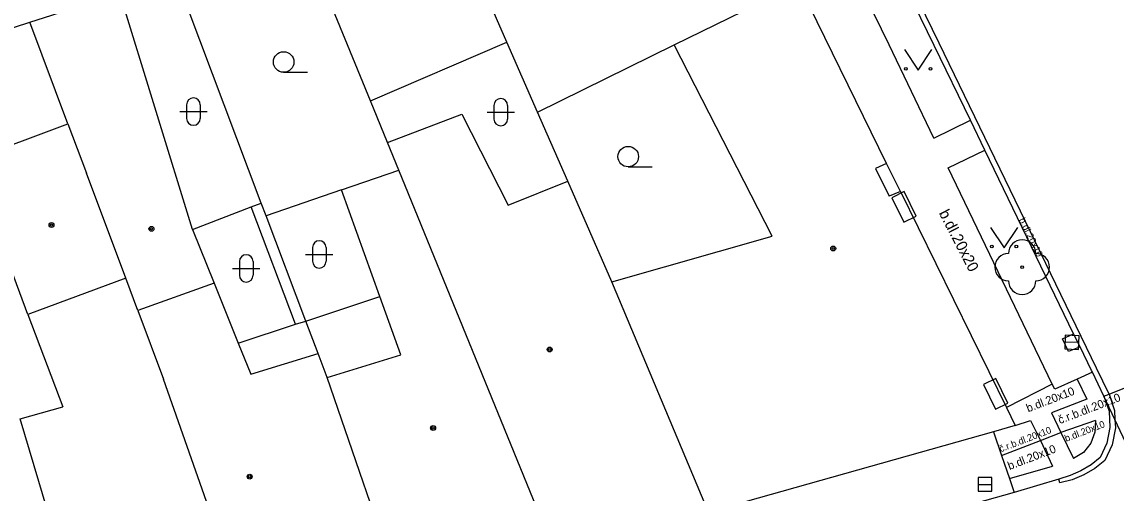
# Model space of a CAD drawing. Extents: x -595546 to -593986, y -1160845 to -1159202.
# Drawn here: x -595474.42 to -595434.45, y -1160188.2 to -1160170.97 of the extents above; entities that cross this region are included whole.
import ezdxf

# ---------------------------------------------------------------- set-up
doc = ezdxf.new("R2010")
doc.units = 0
for name, color, linetype in [('DOP - kresba z DSPS bez souradnic', 7, 'Continuous'), ('DOP - rozhrani ploch obecne', 7, 'Continuous'), ('Level 22', 7, 'Continuous'), ('Level 24', 7, 'Continuous'), ('Level 27', 7, 'Continuous'), ('Level 36', 7, 'Continuous'), ('Level 39', 7, 'Continuous'), ('Specificka linie pasportu komunikaci', 7, 'Continuous'), ('TM - budovy zdene_ betonove - NP', 7, 'Continuous'), ('TM - budovy zdene_ betonove - VP', 7, 'Continuous'), ('TM - chodniky - VP', 7, 'Continuous'), ('TM - komunikace - VP', 7, 'Continuous'), ('TM - letecke snimky - pomocna linie', 7, 'Continuous'), ('TM - pomocna konstrukcni linie', 7, 'Continuous'), ('TM - popis povrchu', 7, 'Continuous'), ('TM - rozhrani mezi zpev. plochami mezi sebou - VP', 7, 'Continuous'), ('TM - vstup do budovy - zdene_ betonove', 7, 'Continuous')]:
    doc.layers.add(name, color=color, linetype=linetype)

msp = doc.modelspace()

# ---------------------------------------------------------------- linework, layer by layer
at = {"layer": 'DOP - kresba z DSPS bez souradnic'}
for points in [[(-595461.69, -1160173.86), (-595456.7, -1160171.72)], [(-595462.75, -1160177.11), (-595465.5, -1160178.06)], [(-595466.04, -1160177.74), (-595465.68, -1160177.6)], [(-595468.19, -1160178.57), (-595466.04, -1160177.74)], [(-595464.43, -1160182.02), (-595466.04, -1160177.74)], [(-595464.05, -1160181.91), (-595461.34, -1160181.01)], [(-595466.52, -1160182.72), (-595464.43, -1160182.02)], [(-595464.43, -1160182.02), (-595464.05, -1160181.91)]]:
    msp.add_lwpolyline(points, dxfattribs=at)
at = {"layer": 'DOP - rozhrani ploch obecne'}
for points in [[(-595456.7, -1160171.72), (-595459.14, -1160166.13)], [(-595461.69, -1160173.86), (-595464.18, -1160167.77)], [(-595465.68, -1160177.6), (-595468.81, -1160169.27)], [(-595474.13, -1160170.99), (-595470.84, -1160169.92)], [(-595478.73, -1160172.48), (-595474.13, -1160170.99)], [(-595472.74, -1160174.7), (-595474.13, -1160170.99)], [(-595455.59, -1160174.27), (-595456.7, -1160171.72)], [(-595455.59, -1160174.27), (-595450.59, -1160171.81)], [(-595461.06, -1160175.39), (-595461.69, -1160173.86)], [(-595454.48, -1160176.8), (-595455.59, -1160174.27)], [(-595465.5, -1160178.06), (-595465.68, -1160177.6)], [(-595464.05, -1160181.91), (-595465.5, -1160178.06)], [(-595463.6, -1160183.1), (-595464.05, -1160181.91)]]:
    msp.add_lwpolyline(points, dxfattribs=at)
at = {"layer": 'Level 22'}
msp.add_circle((-595437.88, -1160179.94), 0.05, dxfattribs=at)
for centre, start, end in [((-595437.88, -1160179.44), 0, 180), ((-595438.38, -1160179.94), 90, 270), ((-595437.38, -1160179.94), 270, 90), ((-595437.88, -1160180.44), 180, 0)]:
    msp.add_arc(centre, 0.5, start, end, dxfattribs=at)
at = {"layer": 'Level 24'}
for points in [[(-595441.751, -1160178.079), (-595442.191, -1160177.181), (-595442.64, -1160177.401), (-595442.2, -1160178.299)], [(-595438.403, -1160184.908), (-595438.843, -1160184.01), (-595439.292, -1160184.23), (-595438.852, -1160185.128)]]:
    msp.add_lwpolyline(points, close=True, dxfattribs=at)
at = {"layer": 'Level 27'}
for p, q in [((-595435.81, -1160182.699), (-595436.31, -1160182.681)), ((-595439.48, -1160187.88), (-595438.98, -1160187.88))]:
    msp.add_line(p, q, dxfattribs=at)
for points in [[(-595435.801, -1160182.449), (-595436.301, -1160182.431), (-595436.319, -1160182.931), (-595435.819, -1160182.949)], [(-595439.48, -1160188.13), (-595438.98, -1160188.13), (-595438.98, -1160187.63), (-595439.48, -1160187.63)]]:
    msp.add_lwpolyline(points, close=True, dxfattribs=at)
at = {"layer": 'Level 36'}
for p, q in [((-595464.86, -1160172.815), (-595463.985, -1160172.815)), ((-595468.406, -1160174.006), (-595468.406, -1160174.506)), ((-595467.906, -1160174.006), (-595467.906, -1160174.506)), ((-595457.176, -1160174.026), (-595457.176, -1160174.526)), ((-595456.676, -1160174.026), (-595456.676, -1160174.526)), ((-595468.656, -1160174.256), (-595467.656, -1160174.256)), ((-595457.426, -1160174.276), (-595456.426, -1160174.276)), ((-595452.27, -1160176.275), (-595451.395, -1160176.275)), ((-595463.806, -1160179.226), (-595463.806, -1160179.726)), ((-595463.306, -1160179.226), (-595463.306, -1160179.726)), ((-595464.056, -1160179.476), (-595463.056, -1160179.476)), ((-595466.726, -1160179.986), (-595465.726, -1160179.986)), ((-595466.476, -1160179.736), (-595466.476, -1160180.236)), ((-595465.976, -1160179.736), (-595465.976, -1160180.236))]:
    msp.add_line(p, q, dxfattribs=at)
for points in [[(-595442.18, -1160171.99), (-595441.68, -1160172.74), (-595441.18, -1160171.99)], [(-595439.04, -1160178.49), (-595438.54, -1160179.24), (-595438.04, -1160178.49)]]:
    msp.add_lwpolyline(points, dxfattribs=at)
for centre, radius in [((-595464.86, -1160172.44), 0.375), ((-595442.13, -1160172.69), 0.05), ((-595441.231, -1160172.69), 0.05), ((-595452.27, -1160175.9), 0.375), ((-595438.99, -1160179.19), 0.05), ((-595438.091, -1160179.19), 0.05)]:
    msp.add_circle(centre, radius, dxfattribs=at)
for centre, start, end in [((-595468.156, -1160174.006), 0, 180), ((-595456.926, -1160174.026), 0, 180), ((-595468.156, -1160174.506), 180, 0), ((-595456.926, -1160174.526), 180, 0), ((-595463.556, -1160179.226), 0, 180), ((-595466.226, -1160179.736), 0, 180), ((-595463.556, -1160179.726), 180, 0), ((-595466.226, -1160180.236), 180, 0)]:
    msp.add_arc(centre, 0.25, start, end, dxfattribs=at)
at = {"layer": 'Level 39'}
for centre, radius in [((-595473.34, -1160178.4), 0.09), ((-595473.34, -1160178.4), 0.0398), ((-595469.69, -1160178.54), 0.09), ((-595469.69, -1160178.54), 0.0398), ((-595444.78, -1160179.26), 0.09), ((-595444.78, -1160179.26), 0.0398), ((-595455.14, -1160182.95), 0.09), ((-595455.14, -1160182.95), 0.0398), ((-595459.4, -1160185.82), 0.09), ((-595459.4, -1160185.82), 0.0398), ((-595466.1, -1160187.6), 0.09), ((-595466.1, -1160187.6), 0.0398)]:
    msp.add_circle(centre, radius, dxfattribs=at)
at = {"layer": 'Specificka linie pasportu komunikaci'}
for points in [[(-595434.7, -1160184.58), (-595428.76, -1160182.2)], [(-595434.89, -1160184.66), (-595434.7, -1160184.58)], [(-595434.49, -1160185.51), (-595434.89, -1160184.66)], [(-595430.18, -1160194.66), (-595434.49, -1160185.51)]]:
    msp.add_lwpolyline(points, dxfattribs=at)
at = {"layer": 'TM - budovy zdene_ betonove - NP'}
for points in [[(-595442.83, -1160176.15), (-595443.24, -1160176.33)], [(-595443.24, -1160176.33), (-595442.74, -1160177.35)], [(-595442.32, -1160177.18), (-595442.74, -1160177.35)]]:
    msp.add_lwpolyline(points, dxfattribs=at)
at = {"layer": 'TM - budovy zdene_ betonove - VP'}
for points in [[(-595450.59, -1160171.81), (-595446.05, -1160169.58)], [(-595442.83, -1160176.15), (-595445.93, -1160169.82)], [(-595447.01, -1160178.81), (-595450.59, -1160171.81)], [(-595461.06, -1160175.39), (-595458.35, -1160174.35)], [(-595458.35, -1160174.35), (-595456.66, -1160177.67)], [(-595476.3, -1160176.03), (-595472.74, -1160174.7)], [(-595472.74, -1160174.7), (-595472.06, -1160176.51)], [(-595460.65, -1160176.4), (-595461.06, -1160175.39)], [(-595474.2, -1160181.67), (-595476.3, -1160176.03)], [(-595462.75, -1160177.11), (-595460.65, -1160176.4)], [(-595454.92, -1160190.44), (-595460.65, -1160176.4)], [(-595470.63, -1160180.34), (-595472.06, -1160176.51)], [(-595456.66, -1160177.67), (-595454.48, -1160176.8)], [(-595452.87, -1160180.48), (-595454.48, -1160176.8)], [(-595461.34, -1160181.01), (-595462.75, -1160177.11)], [(-595442.32, -1160177.18), (-595438.45, -1160185.07)], [(-595468.19, -1160178.57), (-595467.4, -1160180.53)], [(-595452.87, -1160180.48), (-595447.01, -1160178.81)], [(-595470.63, -1160180.34), (-595474.2, -1160181.67)], [(-595470.19, -1160181.53), (-595470.63, -1160180.34)], [(-595449.34, -1160188.9), (-595452.87, -1160180.48)], [(-595467.4, -1160180.53), (-595470.19, -1160181.53)], [(-595467.4, -1160180.53), (-595466.52, -1160182.72)], [(-595460.58, -1160183.15), (-595461.34, -1160181.01)], [(-595474.2, -1160181.67), (-595472.93, -1160185.05)], [(-595470.19, -1160181.53), (-595469.25, -1160184.04)], [(-595466.52, -1160182.72), (-595466.06, -1160183.85)], [(-595466.06, -1160183.85), (-595463.6, -1160183.1)], [(-595463.27, -1160183.98), (-595463.6, -1160183.1)], [(-595463.27, -1160183.98), (-595460.58, -1160183.15)], [(-595465.95, -1160193.43), (-595469.25, -1160184.04)], [(-595460.51, -1160192.01), (-595463.27, -1160183.98)], [(-595474.49, -1160185.48), (-595472.93, -1160185.05)], [(-595438.45, -1160185.07), (-595438.13, -1160185.73)], [(-595471.66, -1160194.98), (-595474.49, -1160185.48)], [(-595438.92, -1160185.96), (-595449.34, -1160188.9)], [(-595438.13, -1160185.73), (-595438.92, -1160185.96)]]:
    msp.add_lwpolyline(points, dxfattribs=at)
at = {"layer": 'TM - chodniky - VP'}
for points in [[(-595441.11, -1160175.22), (-595442.74, -1160171.82), (-595444.15, -1160168.92)], [(-595441.11, -1160175.22), (-595439.77, -1160174.57)], [(-595440.58, -1160176.31), (-595439.24, -1160175.67)], [(-595436.78, -1160184.22), (-595440.58, -1160176.31)], [(-595435.87, -1160184.03), (-595436.69, -1160184.4), (-595436.78, -1160184.22)], [(-595435.31, -1160183.78), (-595435.87, -1160184.03)]]:
    msp.add_lwpolyline(points, dxfattribs=at)
at = {"layer": 'TM - komunikace - VP'}
for points in [[(-595439.77, -1160174.57), (-595441.09, -1160171.84), (-595442.32, -1160169.31), (-595442.77, -1160168.39), (-595442.83, -1160168.26)], [(-595439.24, -1160175.67), (-595439.77, -1160174.57)], [(-595436, -1160182.38), (-595439.24, -1160175.67)], [(-595435.76, -1160182.85), (-595436.18, -1160183.02), (-595436.4, -1160182.56), (-595436, -1160182.38)], [(-595435.31, -1160183.78), (-595435.34, -1160183.72), (-595435.76, -1160182.85)], [(-595434.89, -1160184.66), (-595435.31, -1160183.78)], [(-595434.89, -1160184.66), (-595434.7, -1160185.21), (-595434.67, -1160185.8), (-595434.78, -1160186.37), (-595435.03, -1160186.9)], [(-595435.03, -1160186.9), (-595435.36, -1160187.17), (-595435.73, -1160187.39), (-595436.12, -1160187.56), (-595436.54, -1160187.69)], [(-595436.54, -1160187.69), (-595438.17, -1160188.18)], [(-595438.17, -1160188.18), (-595476.8, -1160199.04)]]:
    msp.add_lwpolyline(points, dxfattribs=at)
at = {"layer": 'TM - letecke snimky - pomocna linie'}
msp.add_lwpolyline([(-595468.19, -1160178.57), (-595470.84, -1160169.92)], dxfattribs=at)
at = {"layer": 'TM - pomocna konstrukcni linie'}
msp.add_lwpolyline([(-595435.76, -1160182.85), (-595436, -1160182.38)], dxfattribs=at)
at = {"layer": 'TM - rozhrani mezi zpev. plochami mezi sebou - VP'}
for points in [[(-595440.91, -1160171.75), (-595442.14, -1160169.22), (-595442.59, -1160168.3), (-595444.11, -1160165.17), (-595444.54, -1160164.26), (-595446.08, -1160161.11), (-595447.61, -1160157.96), (-595448.05, -1160157.06), (-595449.11, -1160154.88), (-595449.54, -1160153.97), (-595451.52, -1160149.92), (-595452.9, -1160147.06)], [(-595435.16, -1160183.63), (-595440.91, -1160171.75)], [(-595434.7, -1160184.58), (-595435.16, -1160183.63)], [(-595435.87, -1160184.03), (-595435.51, -1160184.77), (-595436.81, -1160185.27), (-595436.47, -1160185.99)], [(-595436.78, -1160184.22), (-595438.45, -1160185.07)], [(-595434.7, -1160184.58), (-595434.51, -1160185.18), (-595434.49, -1160185.51)], [(-595438.13, -1160185.73), (-595437.57, -1160185.54), (-595437.21, -1160186.28)], [(-595435.2, -1160185.54), (-595436.47, -1160185.99)], [(-595435.2, -1160185.54), (-595435.22, -1160185.97), (-595435.37, -1160186.37), (-595435.64, -1160186.71), (-595436, -1160186.94)], [(-595434.49, -1160185.51), (-595434.47, -1160185.81), (-595434.59, -1160186.44), (-595434.86, -1160187.01)], [(-595438.92, -1160185.96), (-595438.63, -1160186.82)], [(-595437.21, -1160186.28), (-595436.47, -1160185.99)], [(-595436.47, -1160185.99), (-595436, -1160186.94)], [(-595438.63, -1160186.82), (-595437.21, -1160186.28)], [(-595437.21, -1160186.28), (-595436.77, -1160187.21)], [(-595438.63, -1160186.82), (-595438.34, -1160187.67)], [(-595438.34, -1160187.67), (-595436.77, -1160187.21)], [(-595434.86, -1160187.01), (-595435.22, -1160187.3), (-595435.62, -1160187.53)], [(-595438.34, -1160187.67), (-595438.17, -1160188.18)], [(-595435.62, -1160187.53), (-595436.05, -1160187.71), (-595436.5, -1160187.82)], [(-595436.5, -1160187.82), (-595436.54, -1160187.69)]]:
    msp.add_lwpolyline(points, dxfattribs=at)
at = {"layer": 'TM - vstup do budovy - zdene_ betonove'}
msp.add_lwpolyline([(-595442.32, -1160177.18), (-595442.83, -1160176.15)], dxfattribs=at)

# ---------------------------------------------------------------- texts
at = {"layer": 'TM - popis povrchu'}
for s, height, rotation, p in [('b.dl.20x20', 0.4, 297.3424, (-595440.93, -1160177.96)), ('b.dl.20x10', 0.25, 296.187, (-595438.01, -1160178.21)), ('b.dl.20x10', 0.3, 21, (-595437.66, -1160185.25)), ('č.r.b.dl.20x10', 0.3, 21, (-595436.5, -1160185.68)), ('b.dl.20x10', 0.25, 21, (-595436.27, -1160186.33)), ('č.r.b.dl.20x10', 0.25, 21, (-595438.66, -1160186.71)), ('b.dl.20x10', 0.3, 21, (-595438.34, -1160187.36))]:
    msp.add_text(s, height=height, rotation=rotation, dxfattribs=at).set_placement(p)

doc.saveas('drawing.dxf')
